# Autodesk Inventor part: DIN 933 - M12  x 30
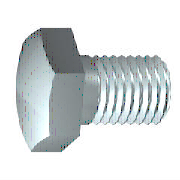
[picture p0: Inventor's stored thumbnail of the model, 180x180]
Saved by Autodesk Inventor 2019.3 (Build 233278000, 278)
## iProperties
Created: 2018-01
Part Number: DIN 933 - M12  x 30
Material: Ocel, měkká
Description: Šestihranný šroub
Document SubType Name: Modeling
Standard: DIN 933
Designer: B-hon
Standards Organization: DIN
Language: cs-CZ
Size Designation: M12  x 30
Categories: <MemberInstance><Categories><Category DisplayName="Spojovací materiál" InternalName="e4da775c-781d-43d5-af7c-5136215cf5a6" Mnemonic="FSTN"><Category DisplayName
Density: 7.85 g/cm^3
Appearance: Pololeštěná
IsCustomPart: 0
Author: B-hon
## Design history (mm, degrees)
sketch "Náčrt1"
  geometry: L1 (0, 8.6)-(0, 5.526); L2 (5.25, 6)-(30, 6); L3 (30, 6)-(30, 0); L4 (30, 0)-(-0.6, 0); L5 (-6.72, 0)-(36.12, 0) reference; L6 (-0.6, 0)-(-0.6, 8.6); L7 (-0.6, 8.6)-(0, 8.6); L8 (5.25, 6)-(4.176, 5.526); L9 (4.176, 5.526)-(0, 5.526); L10 (0, -1.72)-(0, 10.32) reference
  constraints: 16 end point, 2 collinear, 2 perpendicular, 1 parallel
  dimensions: "d0" = 30 distance between parallel lines of L3 L1 (= NLG); "d1" = 24.75 distance from line of L2.start L3 (= GEL); "d2" = 12 diameter of L2 L4 (= GD); "d9" = 0.6001 distance between parallel lines of L6 L1 (computed from SD); "d10" = 17.2 diameter of L7 L4 (= SD2); "d13" = 1.07364 horizontal distance of L2.start L8.end (computed from GAL); "d14" = 11.05279 diameter of L9 L4 (= BDM)
revolve "Těleso" sketch "Náčrt1" stored, may be unused: angle "d12" = 90 deg
sketch "Náčrt2"
  geometry: L1 (0, 10.97)-(9.5, 5.485); L2 (9.5, 5.485)-(9.5, -5.485); L3 (9.5, -5.485)-(0, -10.97); L4 (0, -10.97)-(-9.5, -5.485); L5 (-9.5, -5.485)-(-9.5, 5.485); L6 (-9.5, 5.485)-(0, 10.97); 2 further points
  constraints: 12 end point, 1 coincident, 1 vertical, 11 other
  dimensions: "d11" = 19 distance between parallel lines of L5 L2 (= SW)
extrude "Hlava" join sketch "Náčrt2" distance "d3" = 6.9 (= KOH - SD); taper "d4" = 0 deg
sketch "Náčrt4"
  geometry: L1 (-7.5, 9.5)-(-7.5, 10.97); L2 (-7.5, 10.97)-(-6.652, 10.97); L3 (-6.652, 10.97)-(-7.5, 9.5); L4 (-8.88, 0)-(0.78, 0) reference; L5 (-0.6, 10.97)-(-7.5, 10.97) reference; L6 (-7.5, 5.485)-(-7.5, 10.97) reference
  constraints: 6 end point, 2 collinear, 1 perpendicular, 1 vertical
  dimensions: "d5" = 30 deg angle of L3 L1 (= ANG1); "d19" = 19 diameter of L1.start L4 (= SW0)
revolve "Zkosení1" sketch "Náčrt4" stored, may be unused: angle "d21" = 90 deg
workplane "Work Plane1"
body "Solid1"
feature "Závit" dims "d15" = 24.75 (= GEL), "d16" = 0
chamfer "Zkosení2" distance "d6" = 1.07354 (= -0.5 x SPD + 0.5 x GD); stored, may be unused: second distance "d7" = 1.07364 (computed from GUL), angle "d55" = 45 deg
other parameters: "NLG" = 30 [user parameter; used in 1 equation term], "GD" = 12 (= NND) [user parameter; used in 2 equation terms], "BDM" = 11.05279 [user parameter; used in 1 equation term], "KOH" = 7.5 [user parameter; used in 1 equation term], "GEL" = 24.75 [user parameter; used in 2 equation terms], "SW" = 19 [user parameter; used in 2 equation terms], "SW0" = 19 [user parameter; used in 1 equation term], "SPD" = 9.85293 (= NND - 1.2269 x PTC) [user parameter; used in 1 equation term], "SD2" = 17.2 [user parameter; used in 1 equation term], "SD" = 0.6 [user parameter; used in 2 equation terms], "ANG1" = 30 deg [user parameter; used in 1 equation term], "GAL" = 1.07354 (= 0.61345 x PTC) [user parameter; used in 1 equation term], "GUL" = 1.07354 (= 0.61345 x PTC) [user parameter; used in 1 equation term], "d8" = 0, "RR" = 0.6 [user parameter], "d57" = 0, "d58" = 0, "TPU" = 5.71429 (computed from PTC) [user parameter], "GD1" = 9.85293 (= THREADDIA - 1.2269 x PTC) [user parameter], "THREADDIA" = 12 [user parameter; used in 1 equation term], "TOA" = 30 deg [user parameter], "PTC" = 1.75 [user parameter; used in 5 equation terms], "NND" = 12 [user parameter; used in 2 equation terms], "E0" = 21.945 (= 1.155 x SW) [user parameter]
